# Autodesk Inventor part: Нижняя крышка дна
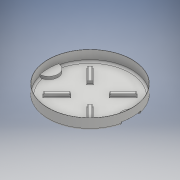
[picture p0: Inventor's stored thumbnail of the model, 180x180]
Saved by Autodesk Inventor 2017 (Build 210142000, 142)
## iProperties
Part Number: Нижняя крышка дна
Material: Типовые
Document SubType Name: Modeling
Designer: MaxZam
Density: 1 g/cm^3
Appearance: По умолчанию
Author: MaxZam
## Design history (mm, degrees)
sketch "Эскиз1"
  geometry: C1 r 223.5 at (0, 0); 1 further point
  constraints: 1 centre point, 1 coincident
  dimensions: "d0" = 447 diameter of C1
extrude "Выдавливание1" new body sketch "Эскиз1" distance "d1" = 2; taper "d2" = 0 deg
sketch "Эскиз2"
  geometry: C1 r 223.5 at (0, 0); C2 r 222 at (0, 0); 1 further point
  constraints: 2 centre point, 2 coincident
  dimensions: "d3" = 447 diameter of C1; "d4" = 444 diameter of C2
extrude "Выдавливание2" join sketch "Эскиз2" distance "d5" = 56; taper "d6" = 0 deg
fillet "Сопряжение1" dims "d7" = 10
sketch "Эскиз3"
  geometry: L1 (223.5, 0)-(-222, 0); A1 r 223.5 centre (0, 0) between (-217.835, -50) and (223.5, 0) reference; A2 r 50.047 centre (-220, 0) between (-217.835, -50) and (-217.835, 50); A3 r 50.047 centre (220, 0) between (217.835, 50) and (217.835, -50); A4 r 223.5 centre (2.056, 10) between (-217.835, 50) and (-213.35, -49.603); A5 r 223.5 centre (0, 0) between (217.835, -50) and (217.835, 50); 2 further points
  constraints: 15 point on circle, 4 centre point, 2 end point, 1 equal radius, 1 horizontal, 1 horizontal alignment, 1 other
  dimensions: "d9" = 50 distance from line of A2.end L1; "d10" = 50 distance from line of A1.start L1; "d11" = 0 distance from line of point (0, 0) L1; "d12" = 220 distance of A2.centre A1.centre; "d13" = 50 distance from line of L1 A3.start; "d14" = 50 distance from line of L1 A3.end; "d15" = 220 distance of A1.centre A3.centre
extrude "Выдавливание3" join sketch "Эскиз3" distance "d16" = 15; taper "d17" = 0 deg
sketch "Эскиз4"
  geometry: A1 r 223.5 centre (0, 0) between (217.835, -50) and (217.835, 50) reference; A2 r 50.047 centre (220, 0) between (206.453, 48.178) and (206.453, -48.178) reference; A3 r 223.5 centre (0, 0) between (-217.835, 50) and (-217.835, -50) reference; A4 r 50.047 centre (-220, 0) between (-206.453, -48.178) and (-206.453, 48.178) reference; A5 r 223.5 centre (0, 0) between (217.835, -50) and (217.835, 50); A6 r 223.5 centre (0, 0) between (-217.835, 50) and (-217.835, -50); A7 r 48.651 centre (-221.5, 0) between (-218.166, -48.537) and (-218.166, 48.537); A8 r 48.651 centre (221.5, 0) between (218.166, 48.537) and (218.166, -48.537); 2 further points
  constraints: 12 point on circle, 4 centre point, 5 other
  dimensions: "d18" = 0 vertical distance of A7.centre A4.centre; "d19" = 1.5 distance of A7.centre A4.centre; "d20" = 0 vertical distance of A2.centre A8.centre; "d21" = 1.5 distance of A2.centre A8.centre; "d22" = 1.5 distance of A8.end A1.start; "d23" = 1.5 distance of A7.start A3.end
extrude "Выдавливание4" cut sketch "Эскиз4" distance "d24" = 13.5; taper "d25" = 0 deg
fillet "Сопряжение2" dims "d26" = 10
fillet "Сопряжение3" dims "d27" = 9
sketch "Эскиз5"
  geometry: L1 (116.673, -130.815)-(-130.815, 116.673); L2 (-130.815, 116.673)-(-116.673, 130.815); L3 (-116.673, 130.815)-(130.815, -116.673); L4 (130.815, -116.673)-(116.673, -130.815); L5 (130.815, 116.673)-(-116.673, -130.815); L6 (-116.673, -130.815)-(-130.815, -116.673); L7 (-130.815, -116.673)-(116.673, 130.815); L8 (116.673, 130.815)-(130.815, 116.673); L9 (28.827, 0)-(-21.737, 0); L10 (-45.962, -60.104)-(-60.104, -45.962); L11 (-60.104, 45.962)-(-45.962, 60.104); L12 (60.104, -45.962)-(45.962, -60.104); L13 (45.962, 60.104)-(60.104, 45.962); 1 further point
  constraints: 26 end point, 8 point on line, 6 perpendicular, 1 horizontal
  dimensions: "d28" = 10 distance from line of L1 point (0, 0); "d29" = 10 distance from line of point (0, 0) L3; "d30" = 0 deg angle of L1 L3; "d31" = 90 deg angle of L3 L4; "d32" = 10 distance from line of L5 point (0, 0); "d33" = 10 distance from line of point (0, 0) L7; "d34" = 90 deg angle of L6 L7; "d35" = 90 deg angle of L5 L8; "d36" = 45 deg angle of L9 L3; "d37" = 45 deg angle of L7 L9; "d38" = 350 distance of L1.start L1.end; "d39" = 350 distance of L5.start L5.end; "d40" = 175 distance from line of L6 point (0, 0); "d41" = 175 distance from line of L4 point (0, 0); "d42" = 75 distance from line of L12 point (0, 0); "d43" = 75 distance from line of L10 point (0, 0); "d44" = 75 distance from line of point (0, 0) L11; "d45" = 75 distance from line of L13 point (0, 0)
extrude "Выдавливание5" join sketch "Эскиз5" distance "d46" = 15; taper "d47" = 0 deg
sketch "Эскиз6"
  geometry: L1 (-116.673, -130.815)-(-130.815, -116.673) reference; L2 (-130.815, -116.673)-(-60.104, -45.962) reference; L3 (-60.104, -45.962)-(-45.962, -60.104) reference; L4 (-45.962, -60.104)-(-116.673, -130.815) reference; L5 (116.673, -130.815)-(45.962, -60.104) reference; L6 (45.962, -60.104)-(60.104, -45.962) reference; L7 (60.104, -45.962)-(130.815, -116.673) reference; L8 (130.815, -116.673)-(116.673, -130.815) reference; L9 (130.815, 116.673)-(60.104, 45.962) reference; L10 (60.104, 45.962)-(45.962, 60.104) reference; L11 (45.962, 60.104)-(116.673, 130.815) reference; L12 (116.673, 130.815)-(130.815, 116.673) reference; L13 (-130.815, 116.673)-(-116.673, 130.815) reference; L14 (-116.673, 130.815)-(-45.962, 60.104) reference; L15 (-45.962, 60.104)-(-60.104, 45.962) reference; L16 (-60.104, 45.962)-(-130.815, 116.673) reference; L17 (-116.673, -128.693)-(-128.693, -116.673); L18 (-128.693, -116.673)-(-60.104, -48.083); L19 (-60.104, -48.083)-(-48.083, -60.104); L20 (-48.083, -60.104)-(-116.673, -128.693); L21 (-60.104, 48.083)-(-128.693, 116.673); L22 (-128.693, 116.673)-(-116.673, 128.693); L23 (-116.673, 128.693)-(-48.083, 60.104); L24 (-48.083, 60.104)-(-60.104, 48.083); L25 (60.104, 48.083)-(48.083, 60.104); L26 (48.083, 60.104)-(116.673, 128.693); L27 (116.673, 128.693)-(128.693, 116.673); L28 (128.693, 116.673)-(60.104, 48.083); L29 (116.673, -128.693)-(48.083, -60.104); L30 (48.083, -60.104)-(60.104, -48.083); L31 (60.104, -48.083)-(128.693, -116.673); L32 (128.693, -116.673)-(116.673, -128.693); 1 further point
  constraints: 32 end point, 12 perpendicular, 1 parallel
  dimensions: "d48" = 1.5 distance between parallel lines of L1 L17; "d49" = 1.5 distance between parallel lines of L4 L20; "d50" = 1.5 distance between parallel lines of L2 L18; "d51" = 1.5 distance between parallel lines of L19 L3; "d52" = 1.5 distance between parallel lines of L5 L29; "d53" = 1.5 distance between parallel lines of L8 L32; "d54" = 1.5 distance between parallel lines of L7 L31; "d55" = 1.5 distance between parallel lines of L6 L30; "d56" = 1.5 distance between parallel lines of L10 L25; "d57" = 1.5 distance between parallel lines of L11 L26; "d58" = 1.5 distance between parallel lines of L9 L28; "d59" = 1.5 distance between parallel lines of L12 L27; "d60" = 1.5 distance between parallel lines of L16 L21; "d61" = 1.5 distance between parallel lines of L15 L24; "d62" = 1.5 distance between parallel lines of L14 L23; "d63" = 1.5 distance between parallel lines of L13 L22
extrude "Выдавливание6" cut sketch "Эскиз6" distance "d64" = 13.5; taper "d65" = 0 deg
fillet "Сопряжение4" dims "d66" = 3
node "Твердое тело1"
node "Спроецированная петля1"
node "Спроецированная петля2"
node "Спроецированная петля3"
node "Спроецированная петля4"
